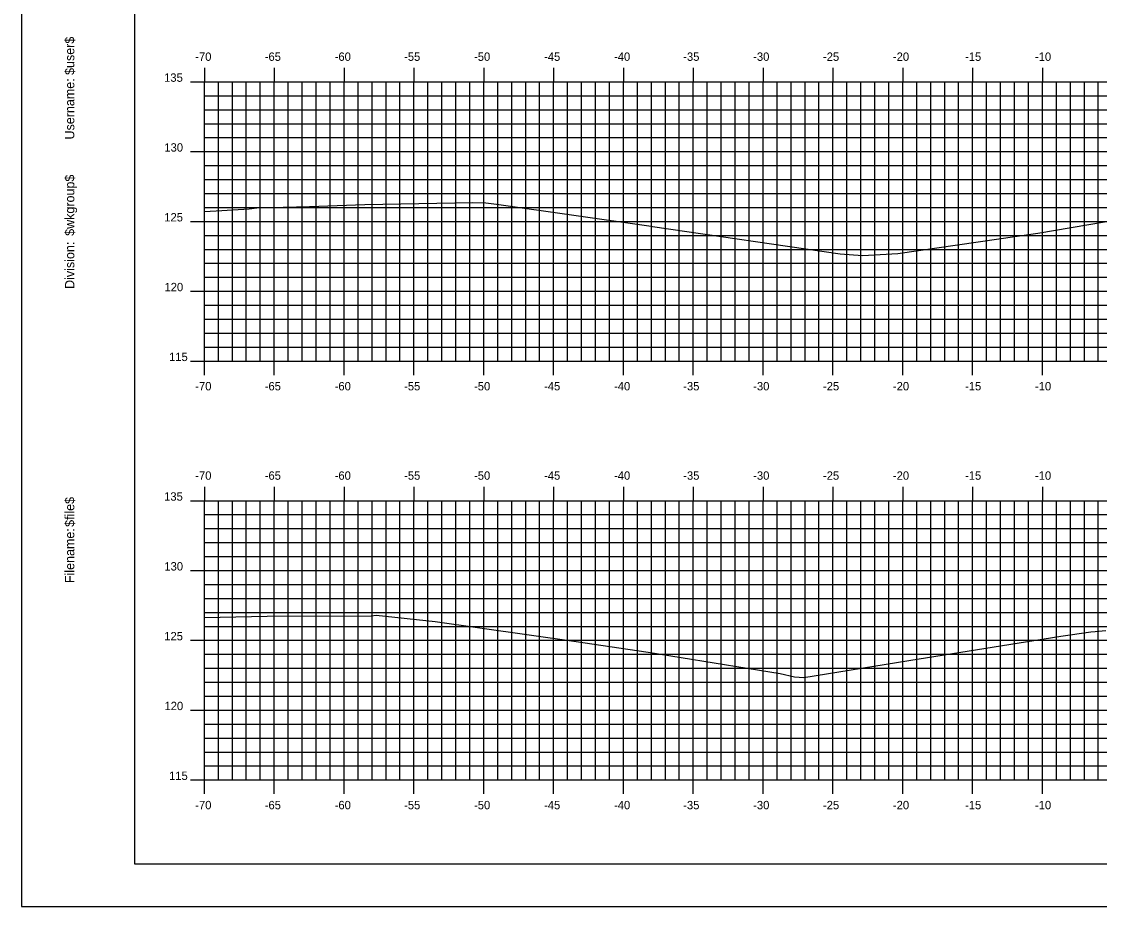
# Model space of a CAD drawing. Extents: x 851738 to 851910, y 365624 to 365734.
# Drawn here: x 851738.4 to 851815.6, y 365624 to 365687.3 of the extents above; entities that cross this region are included whole.
import ezdxf

# ---------------------------------------------------------------- set-up
doc = ezdxf.new("R2010")
doc.units = 0
for name, color, linetype in [('BORDER', 7, 'Continuous'), ('H_V ANNOTATION', 7, 'Continuous'), ('M_Roadway_Centerline', 7, 'Continuous'), ('MAJOR', 7, 'Continuous'), ('MINOR', 7, 'Continuous'), ('PLOT BOUNDARY', 7, 'Continuous'), ('S_Roadway_Centerline', 7, 'Continuous')]:
    doc.layers.add(name, color=color, linetype=linetype)

msp = doc.modelspace()

# ---------------------------------------------------------------- linework, layer by layer
at = {"layer": 'BORDER'}
msp.add_lwpolyline([(851746.522, 365627.027), (851906.522, 365627.027), (851906.522, 365732.027), (851746.522, 365732.027)], close=True, dxfattribs=at)
at = {"layer": 'MAJOR'}
for p, q in [((851751.522, 365684.029), (851751.522, 365683.027)), ((851756.522, 365684.029), (851756.522, 365683.027)), ((851761.522, 365684.029), (851761.522, 365683.027)), ((851766.522, 365684.029), (851766.522, 365683.027)), ((851771.522, 365684.029), (851771.522, 365683.027)), ((851776.522, 365684.029), (851776.522, 365683.027)), ((851781.522, 365684.029), (851781.522, 365683.027)), ((851786.522, 365684.029), (851786.522, 365683.027)), ((851791.522, 365684.029), (851791.522, 365683.027)), ((851796.522, 365684.029), (851796.522, 365683.027)), ((851801.522, 365684.029), (851801.522, 365683.027)), ((851806.522, 365684.029), (851806.522, 365683.027)), ((851811.522, 365684.029), (851811.522, 365683.027)), ((851750.52, 365683.027), (851751.522, 365683.027)), ((851751.522, 365683.027), (851891.522, 365683.027)), ((851751.522, 365663.027), (851751.522, 365683.027)), ((851751.522, 365663.027), (851751.522, 365683.027)), ((851751.522, 365683.027), (851891.522, 365683.027)), ((851756.522, 365663.027), (851756.522, 365683.027)), ((851761.522, 365663.027), (851761.522, 365683.027)), ((851766.522, 365663.027), (851766.522, 365683.027)), ((851771.522, 365663.027), (851771.522, 365683.027)), ((851776.522, 365663.027), (851776.522, 365683.027)), ((851781.522, 365663.027), (851781.522, 365683.027)), ((851786.522, 365663.027), (851786.522, 365683.027)), ((851791.522, 365663.027), (851791.522, 365683.027)), ((851796.522, 365663.027), (851796.522, 365683.027)), ((851801.522, 365663.027), (851801.522, 365683.027)), ((851806.522, 365663.027), (851806.522, 365683.027)), ((851811.522, 365663.027), (851811.522, 365683.027)), ((851750.52, 365678.027), (851751.522, 365678.027)), ((851751.522, 365678.027), (851891.522, 365678.027)), ((851750.52, 365673.027), (851751.522, 365673.027)), ((851751.522, 365673.027), (851891.522, 365673.027)), ((851750.52, 365668.027), (851751.522, 365668.027)), ((851751.522, 365668.027), (851891.522, 365668.027)), ((851750.52, 365663.027), (851751.522, 365663.027)), ((851751.522, 365663.027), (851891.522, 365663.027)), ((851751.522, 365663.027), (851891.522, 365663.027)), ((851751.522, 365662.025), (851751.522, 365663.027)), ((851756.522, 365662.025), (851756.522, 365663.027)), ((851761.522, 365662.025), (851761.522, 365663.027)), ((851766.522, 365662.025), (851766.522, 365663.027)), ((851771.522, 365662.025), (851771.522, 365663.027)), ((851776.522, 365662.025), (851776.522, 365663.027)), ((851781.522, 365662.025), (851781.522, 365663.027)), ((851786.522, 365662.025), (851786.522, 365663.027)), ((851791.522, 365662.025), (851791.522, 365663.027)), ((851796.522, 365662.025), (851796.522, 365663.027)), ((851801.522, 365662.025), (851801.522, 365663.027)), ((851806.522, 365662.025), (851806.522, 365663.027)), ((851811.522, 365662.025), (851811.522, 365663.027)), ((851751.522, 365654.029), (851751.522, 365653.027)), ((851756.522, 365654.029), (851756.522, 365653.027)), ((851761.522, 365654.029), (851761.522, 365653.027)), ((851766.522, 365654.029), (851766.522, 365653.027)), ((851771.522, 365654.029), (851771.522, 365653.027)), ((851776.522, 365654.029), (851776.522, 365653.027)), ((851781.522, 365654.029), (851781.522, 365653.027)), ((851786.522, 365654.029), (851786.522, 365653.027)), ((851791.522, 365654.029), (851791.522, 365653.027)), ((851796.522, 365654.029), (851796.522, 365653.027)), ((851801.522, 365654.029), (851801.522, 365653.027)), ((851806.522, 365654.029), (851806.522, 365653.027)), ((851811.522, 365654.029), (851811.522, 365653.027)), ((851750.52, 365653.027), (851751.522, 365653.027)), ((851751.522, 365653.027), (851891.522, 365653.027)), ((851751.522, 365633.027), (851751.522, 365653.027)), ((851751.522, 365633.027), (851751.522, 365653.027)), ((851751.522, 365653.027), (851891.522, 365653.027)), ((851756.522, 365633.027), (851756.522, 365653.027)), ((851761.522, 365633.027), (851761.522, 365653.027)), ((851766.522, 365633.027), (851766.522, 365653.027)), ((851771.522, 365633.027), (851771.522, 365653.027)), ((851776.522, 365633.027), (851776.522, 365653.027)), ((851781.522, 365633.027), (851781.522, 365653.027)), ((851786.522, 365633.027), (851786.522, 365653.027)), ((851791.522, 365633.027), (851791.522, 365653.027)), ((851796.522, 365633.027), (851796.522, 365653.027)), ((851801.522, 365633.027), (851801.522, 365653.027)), ((851806.522, 365633.027), (851806.522, 365653.027)), ((851811.522, 365633.027), (851811.522, 365653.027)), ((851750.52, 365648.027), (851751.522, 365648.027)), ((851751.522, 365648.027), (851891.522, 365648.027)), ((851750.52, 365643.027), (851751.522, 365643.027)), ((851751.522, 365643.027), (851891.522, 365643.027)), ((851750.52, 365638.027), (851751.522, 365638.027)), ((851751.522, 365638.027), (851891.522, 365638.027)), ((851750.52, 365633.027), (851751.522, 365633.027)), ((851751.522, 365633.027), (851891.522, 365633.027)), ((851751.522, 365633.027), (851891.522, 365633.027)), ((851751.522, 365632.025), (851751.522, 365633.027)), ((851756.522, 365632.025), (851756.522, 365633.027)), ((851761.522, 365632.025), (851761.522, 365633.027)), ((851766.522, 365632.025), (851766.522, 365633.027)), ((851771.522, 365632.025), (851771.522, 365633.027)), ((851776.522, 365632.025), (851776.522, 365633.027)), ((851781.522, 365632.025), (851781.522, 365633.027)), ((851786.522, 365632.025), (851786.522, 365633.027)), ((851791.522, 365632.025), (851791.522, 365633.027)), ((851796.522, 365632.025), (851796.522, 365633.027)), ((851801.522, 365632.025), (851801.522, 365633.027)), ((851806.522, 365632.025), (851806.522, 365633.027)), ((851811.522, 365632.025), (851811.522, 365633.027))]:
    msp.add_line(p, q, dxfattribs=at)
at = {"layer": 'MINOR'}
for p, q in [((851752.522, 365663.027), (851752.522, 365683.027)), ((851753.522, 365663.027), (851753.522, 365683.027)), ((851754.522, 365663.027), (851754.522, 365683.027)), ((851755.522, 365663.027), (851755.522, 365683.027)), ((851757.522, 365663.027), (851757.522, 365683.027)), ((851758.522, 365663.027), (851758.522, 365683.027)), ((851759.522, 365663.027), (851759.522, 365683.027)), ((851760.522, 365663.027), (851760.522, 365683.027)), ((851762.522, 365663.027), (851762.522, 365683.027)), ((851763.522, 365663.027), (851763.522, 365683.027)), ((851764.522, 365663.027), (851764.522, 365683.027)), ((851765.522, 365663.027), (851765.522, 365683.027)), ((851767.522, 365663.027), (851767.522, 365683.027)), ((851768.522, 365663.027), (851768.522, 365683.027)), ((851769.522, 365663.027), (851769.522, 365683.027)), ((851770.522, 365663.027), (851770.522, 365683.027)), ((851772.522, 365663.027), (851772.522, 365683.027)), ((851773.522, 365663.027), (851773.522, 365683.027)), ((851774.522, 365663.027), (851774.522, 365683.027)), ((851775.522, 365663.027), (851775.522, 365683.027)), ((851777.522, 365663.027), (851777.522, 365683.027)), ((851778.522, 365663.027), (851778.522, 365683.027)), ((851779.522, 365663.027), (851779.522, 365683.027)), ((851780.522, 365663.027), (851780.522, 365683.027)), ((851782.522, 365663.027), (851782.522, 365683.027)), ((851783.522, 365663.027), (851783.522, 365683.027)), ((851784.522, 365663.027), (851784.522, 365683.027)), ((851785.522, 365663.027), (851785.522, 365683.027)), ((851787.522, 365663.027), (851787.522, 365683.027)), ((851788.522, 365663.027), (851788.522, 365683.027)), ((851789.522, 365663.027), (851789.522, 365683.027)), ((851790.522, 365663.027), (851790.522, 365683.027)), ((851792.522, 365663.027), (851792.522, 365683.027)), ((851793.522, 365663.027), (851793.522, 365683.027)), ((851794.522, 365663.027), (851794.522, 365683.027)), ((851795.522, 365663.027), (851795.522, 365683.027)), ((851797.522, 365663.027), (851797.522, 365683.027)), ((851798.522, 365663.027), (851798.522, 365683.027)), ((851799.522, 365663.027), (851799.522, 365683.027)), ((851800.522, 365663.027), (851800.522, 365683.027)), ((851802.522, 365663.027), (851802.522, 365683.027)), ((851803.522, 365663.027), (851803.522, 365683.027)), ((851804.522, 365663.027), (851804.522, 365683.027)), ((851805.522, 365663.027), (851805.522, 365683.027)), ((851807.522, 365663.027), (851807.522, 365683.027)), ((851808.522, 365663.027), (851808.522, 365683.027)), ((851809.522, 365663.027), (851809.522, 365683.027)), ((851810.522, 365663.027), (851810.522, 365683.027)), ((851812.522, 365663.027), (851812.522, 365683.027)), ((851813.522, 365663.027), (851813.522, 365683.027)), ((851814.522, 365663.027), (851814.522, 365683.027)), ((851815.522, 365663.027), (851815.522, 365683.027)), ((851751.522, 365682.027), (851891.522, 365682.027)), ((851751.522, 365682.027), (851752.524, 365682.027)), ((851751.522, 365681.027), (851891.522, 365681.027)), ((851751.522, 365681.027), (851752.524, 365681.027)), ((851751.522, 365680.027), (851891.522, 365680.027)), ((851751.522, 365680.027), (851752.524, 365680.027)), ((851751.522, 365679.027), (851891.522, 365679.027)), ((851751.522, 365679.027), (851752.524, 365679.027)), ((851751.522, 365677.027), (851891.522, 365677.027)), ((851751.522, 365677.027), (851752.524, 365677.027)), ((851751.522, 365676.027), (851891.522, 365676.027)), ((851751.522, 365676.027), (851752.524, 365676.027)), ((851751.522, 365675.027), (851891.522, 365675.027)), ((851751.522, 365675.027), (851752.524, 365675.027)), ((851751.522, 365674.027), (851891.522, 365674.027)), ((851751.522, 365674.027), (851752.524, 365674.027)), ((851751.522, 365672.027), (851891.522, 365672.027)), ((851751.522, 365672.027), (851752.524, 365672.027)), ((851751.522, 365671.027), (851891.522, 365671.027)), ((851751.522, 365671.027), (851752.524, 365671.027)), ((851751.522, 365670.027), (851891.522, 365670.027)), ((851751.522, 365670.027), (851752.524, 365670.027)), ((851751.522, 365669.027), (851891.522, 365669.027)), ((851751.522, 365669.027), (851752.524, 365669.027)), ((851751.522, 365667.027), (851891.522, 365667.027)), ((851751.522, 365667.027), (851752.524, 365667.027)), ((851751.522, 365666.027), (851891.522, 365666.027)), ((851751.522, 365666.027), (851752.524, 365666.027)), ((851751.522, 365665.027), (851891.522, 365665.027)), ((851751.522, 365665.027), (851752.524, 365665.027)), ((851751.522, 365664.027), (851891.522, 365664.027)), ((851751.522, 365664.027), (851752.524, 365664.027)), ((851751.522, 365633.027), (851751.522, 365653.027)), ((851752.522, 365633.027), (851752.522, 365653.027)), ((851753.522, 365633.027), (851753.522, 365653.027)), ((851754.522, 365633.027), (851754.522, 365653.027)), ((851755.522, 365633.027), (851755.522, 365653.027)), ((851757.522, 365633.027), (851757.522, 365653.027)), ((851758.522, 365633.027), (851758.522, 365653.027)), ((851759.522, 365633.027), (851759.522, 365653.027)), ((851760.522, 365633.027), (851760.522, 365653.027)), ((851762.522, 365633.027), (851762.522, 365653.027)), ((851763.522, 365633.027), (851763.522, 365653.027)), ((851764.522, 365633.027), (851764.522, 365653.027)), ((851765.522, 365633.027), (851765.522, 365653.027)), ((851767.522, 365633.027), (851767.522, 365653.027)), ((851768.522, 365633.027), (851768.522, 365653.027)), ((851769.522, 365633.027), (851769.522, 365653.027)), ((851770.522, 365633.027), (851770.522, 365653.027)), ((851772.522, 365633.027), (851772.522, 365653.027)), ((851773.522, 365633.027), (851773.522, 365653.027)), ((851774.522, 365633.027), (851774.522, 365653.027)), ((851775.522, 365633.027), (851775.522, 365653.027)), ((851777.522, 365633.027), (851777.522, 365653.027)), ((851778.522, 365633.027), (851778.522, 365653.027)), ((851779.522, 365633.027), (851779.522, 365653.027)), ((851780.522, 365633.027), (851780.522, 365653.027)), ((851782.522, 365633.027), (851782.522, 365653.027)), ((851783.522, 365633.027), (851783.522, 365653.027)), ((851784.522, 365633.027), (851784.522, 365653.027)), ((851785.522, 365633.027), (851785.522, 365653.027)), ((851787.522, 365633.027), (851787.522, 365653.027)), ((851788.522, 365633.027), (851788.522, 365653.027)), ((851789.522, 365633.027), (851789.522, 365653.027)), ((851790.522, 365633.027), (851790.522, 365653.027)), ((851792.522, 365633.027), (851792.522, 365653.027)), ((851793.522, 365633.027), (851793.522, 365653.027)), ((851794.522, 365633.027), (851794.522, 365653.027)), ((851795.522, 365633.027), (851795.522, 365653.027)), ((851797.522, 365633.027), (851797.522, 365653.027)), ((851798.522, 365633.027), (851798.522, 365653.027)), ((851799.522, 365633.027), (851799.522, 365653.027)), ((851800.522, 365633.027), (851800.522, 365653.027)), ((851802.522, 365633.027), (851802.522, 365653.027)), ((851803.522, 365633.027), (851803.522, 365653.027)), ((851804.522, 365633.027), (851804.522, 365653.027)), ((851805.522, 365633.027), (851805.522, 365653.027)), ((851807.522, 365633.027), (851807.522, 365653.027)), ((851808.522, 365633.027), (851808.522, 365653.027)), ((851809.522, 365633.027), (851809.522, 365653.027)), ((851810.522, 365633.027), (851810.522, 365653.027)), ((851812.522, 365633.027), (851812.522, 365653.027)), ((851813.522, 365633.027), (851813.522, 365653.027)), ((851814.522, 365633.027), (851814.522, 365653.027)), ((851815.522, 365633.027), (851815.522, 365653.027)), ((851751.522, 365652.027), (851891.522, 365652.027)), ((851751.522, 365652.027), (851752.524, 365652.027)), ((851751.522, 365651.027), (851891.522, 365651.027)), ((851751.522, 365651.027), (851752.524, 365651.027)), ((851751.522, 365650.027), (851891.522, 365650.027)), ((851751.522, 365650.027), (851752.524, 365650.027)), ((851751.522, 365649.027), (851891.522, 365649.027)), ((851751.522, 365649.027), (851752.524, 365649.027)), ((851751.522, 365647.027), (851891.522, 365647.027)), ((851751.522, 365647.027), (851752.524, 365647.027)), ((851751.522, 365646.027), (851891.522, 365646.027)), ((851751.522, 365646.027), (851752.524, 365646.027)), ((851751.522, 365645.027), (851891.522, 365645.027)), ((851751.522, 365645.027), (851752.524, 365645.027)), ((851751.522, 365644.027), (851891.522, 365644.027)), ((851751.522, 365644.027), (851752.524, 365644.027)), ((851751.522, 365642.027), (851891.522, 365642.027)), ((851751.522, 365642.027), (851752.524, 365642.027)), ((851751.522, 365641.027), (851891.522, 365641.027)), ((851751.522, 365641.027), (851752.524, 365641.027)), ((851751.522, 365640.027), (851891.522, 365640.027)), ((851751.522, 365640.027), (851752.524, 365640.027)), ((851751.522, 365639.027), (851891.522, 365639.027)), ((851751.522, 365639.027), (851752.524, 365639.027)), ((851751.522, 365637.027), (851891.522, 365637.027)), ((851751.522, 365637.027), (851752.524, 365637.027)), ((851751.522, 365636.027), (851891.522, 365636.027)), ((851751.522, 365636.027), (851752.524, 365636.027)), ((851751.522, 365635.027), (851891.522, 365635.027)), ((851751.522, 365635.027), (851752.524, 365635.027)), ((851751.522, 365634.027), (851891.522, 365634.027)), ((851751.522, 365634.027), (851752.524, 365634.027))]:
    msp.add_line(p, q, dxfattribs=at)
at = {"layer": 'PLOT BOUNDARY'}
msp.add_lwpolyline([(851738.429, 365623.968), (851908.429, 365623.968), (851908.429, 365733.968), (851738.429, 365733.968)], close=True, dxfattribs=at)
at = {"layer": 'S_Roadway_Centerline'}
for points in [[(851751.522, 365673.748), (851752.773, 365673.811), (851754.723, 365673.936), (851755.28, 365674.002), (851759.045, 365674.095), (851762.995, 365674.249), (851770.731, 365674.394), (851771.681, 365674.348), (851772.423, 365674.253), (851783.498, 365672.678), (851783.6, 365672.66), (851797.037, 365670.698), (851798.649, 365670.585), (851801.166, 365670.727), (851811.196, 365672.193), (851820.737, 365673.799)], [(851751.522, 365644.656), (851756.004, 365644.745), (851763.464, 365644.772), (851763.819, 365644.819), (851768.053, 365644.374), (851777.964, 365642.957), (851783.3, 365642.182), (851792.752, 365640.645), (851793.764, 365640.424), (851794.447, 365640.373), (851801.965, 365641.57), (851812.832, 365643.319), (851814.979, 365643.626), (851815.305, 365643.654), (851816.061, 365643.732)]]:
    msp.add_lwpolyline(points, dxfattribs=at)

# ---------------------------------------------------------------- texts
at = {"layer": 'BORDER'}
for s, p in [('$user$', (851742.207, 365683.518)), ('Username:', (851742.207, 365678.895)), ('$wkgroup$', (851742.207, 365671.996)), ('Division:', (851742.207, 365668.193)), ('$file$', (851742.207, 365651.152)), ('Filename:', (851742.207, 365647.125))]:
    msp.add_text(s, height=0.6696, rotation=90, dxfattribs=at).set_placement(p)
at = {"layer": 'H_V ANNOTATION'}
for s, p in [('-70', (851750.864, 365684.527)), ('-65', (851755.84, 365684.527)), ('-60', (851760.848, 365684.527)), ('-55', (851765.818, 365684.527)), ('-50', (851770.826, 365684.527)), ('-45', (851775.84, 365684.527)), ('-40', (851780.848, 365684.527)), ('-35', (851785.802, 365684.527)), ('-30', (851790.81, 365684.527)), ('-25', (851795.808, 365684.527)), ('-20', (851800.816, 365684.527)), ('-15', (851805.979, 365684.527)), ('-10', (851810.987, 365684.527)), ('135', (851748.636, 365683.027)), ('130', (851748.652, 365678.027)), ('125', (851748.647, 365673.027)), ('120', (851748.663, 365668.027)), ('115', (851748.989, 365663.027)), ('-70', (851750.864, 365660.927)), ('-65', (851755.84, 365660.927)), ('-60', (851760.848, 365660.927)), ('-55', (851765.818, 365660.927)), ('-50', (851770.826, 365660.927)), ('-45', (851775.84, 365660.927)), ('-40', (851780.848, 365660.927)), ('-35', (851785.802, 365660.927)), ('-30', (851790.81, 365660.927)), ('-25', (851795.808, 365660.927)), ('-20', (851800.816, 365660.927)), ('-15', (851805.979, 365660.927)), ('-10', (851810.987, 365660.927)), ('-70', (851750.864, 365654.527)), ('-65', (851755.84, 365654.527)), ('-60', (851760.848, 365654.527)), ('-55', (851765.818, 365654.527)), ('-50', (851770.826, 365654.527)), ('-45', (851775.84, 365654.527)), ('-40', (851780.848, 365654.527)), ('-35', (851785.802, 365654.527)), ('-30', (851790.81, 365654.527)), ('-25', (851795.808, 365654.527)), ('-20', (851800.816, 365654.527)), ('-15', (851805.979, 365654.527)), ('-10', (851810.987, 365654.527)), ('135', (851748.636, 365653.027)), ('130', (851748.652, 365648.027)), ('125', (851748.647, 365643.027)), ('120', (851748.663, 365638.027)), ('115', (851748.989, 365633.027)), ('-70', (851750.864, 365630.927)), ('-65', (851755.84, 365630.927)), ('-60', (851760.848, 365630.927)), ('-55', (851765.818, 365630.927)), ('-50', (851770.826, 365630.927)), ('-45', (851775.84, 365630.927)), ('-40', (851780.848, 365630.927)), ('-35', (851785.802, 365630.927)), ('-30', (851790.81, 365630.927)), ('-25', (851795.808, 365630.927)), ('-20', (851800.816, 365630.927)), ('-15', (851805.979, 365630.927)), ('-10', (851810.987, 365630.927))]:
    msp.add_text(s, height=0.6, dxfattribs=at).set_placement(p)
at = {"layer": 'M_Roadway_Centerline'}
for s, p in [('C', (851755.275, 365674.002)), ('L', (851755.28, 365673.995))]:
    msp.add_text(s, height=0.0146, dxfattribs=at).set_placement(p)
at = {"layer": 'MAJOR'}
for p in [(851751.518, 365663.027), (851751.518, 365633.027)]:
    msp.add_text('-', height=0.006, dxfattribs=at).set_placement(p)

doc.saveas('drawing.dxf')
